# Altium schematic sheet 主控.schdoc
size 420 x 297 mm; Symbol: Drawing-Symbol_A4; Company: 嘉立创EDA; Version: V1.0; Page Size: A4; @Project Name: FOC; @Update Date: 2026-07-20; @Create Date: 2026-07-20; Device: Drawing-Symbol_A4; @Board Name: Board1; @Page Name: P1; @Create Time: 00:30:57; @Page Count: 3; @Page No: 3; @Schematic Name: Schematic1; @Update Time: 00:30:57; @Assembly Variant: Basic; Border: 1; Title Block Position: 3; Size: A4; Width: 1655; Height: 1170; Region Start: 1; X Region Count: 6; Y Region Count: 4; Blade Width: 10
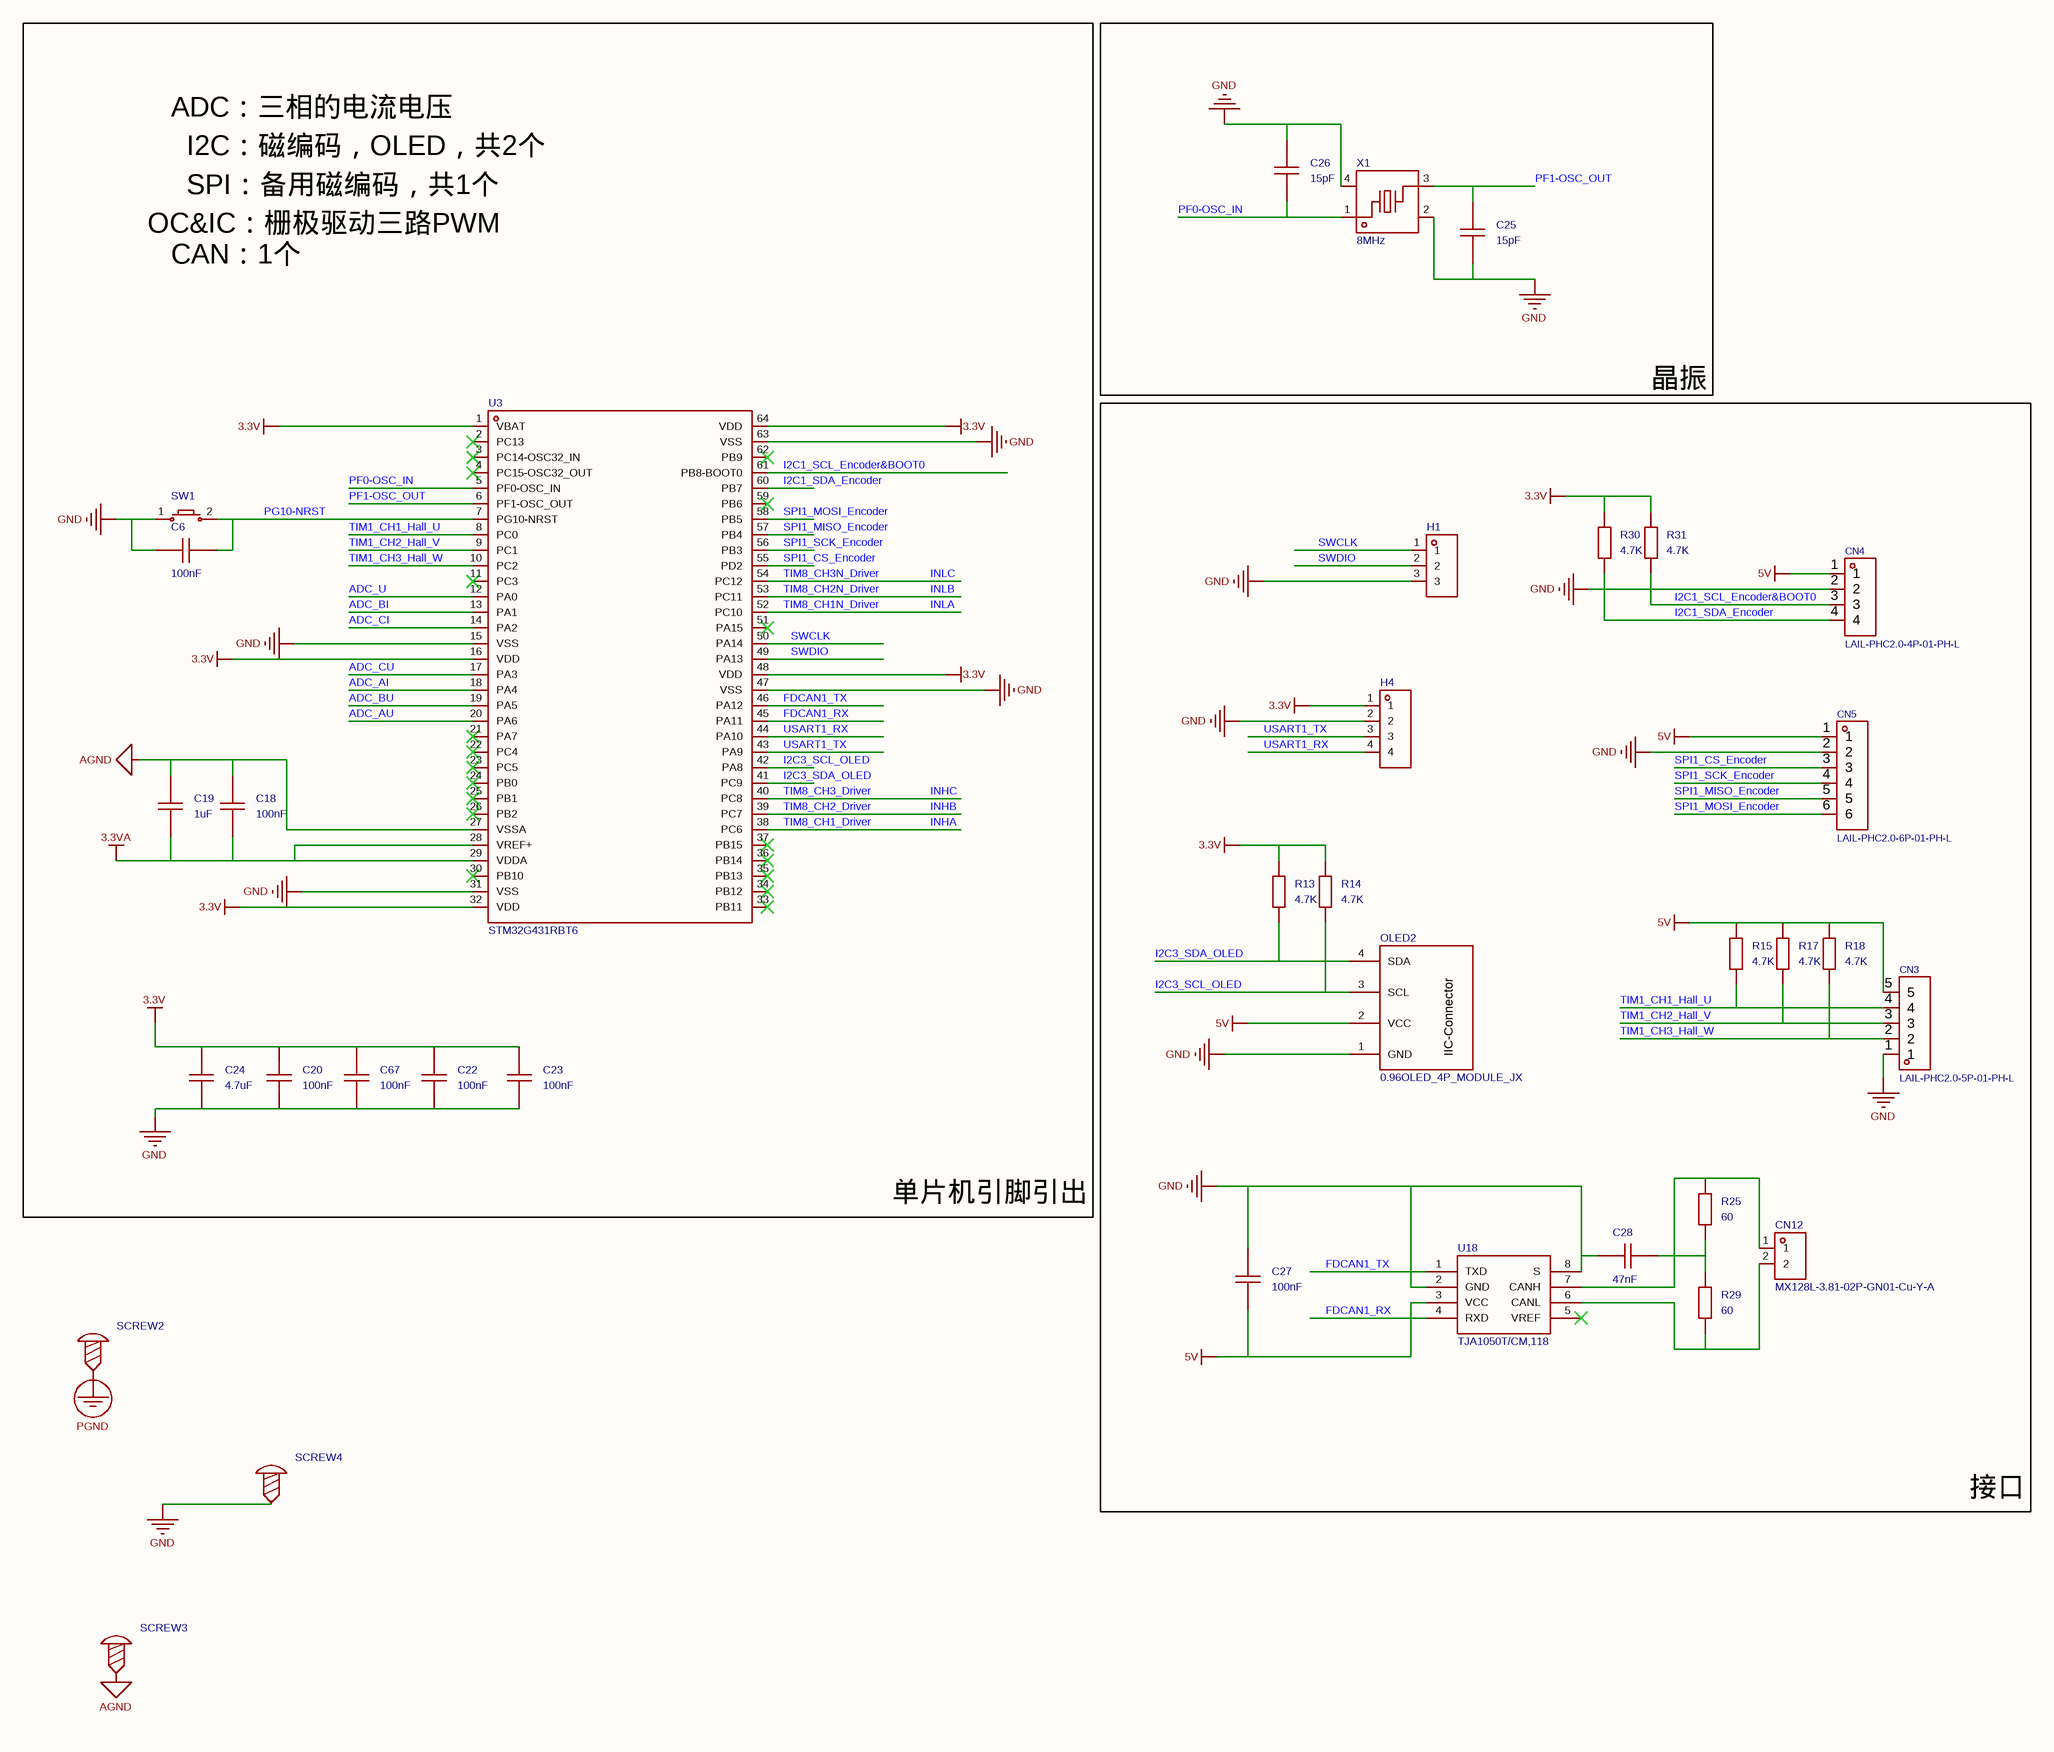
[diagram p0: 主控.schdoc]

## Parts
C6  100nF  [C0603]
C18  100nF  [C0603]
C19  1uF  [C0603]
C20  100nF  [C0603]
C22  100nF  [C0603]
C23  100nF  [C0603]
C24  4.7uF  [C0603]
C25  15pF  [C0603]
C26  15pF  [C0603]
C27  100nF  [C0603]
C28  47nF  [C0603]
C67  100nF  [C0603]
CN3  LAIL-PHC2.0-5P-01-PH-L  [CONN-TH_5P-P2.00_ZX-PH2.0-5PZZ]
CN4  LAIL-PHC2.0-4P-01-PH-L  [CONN-TH_HC-PH-4A-Y-K-10]
CN5  LAIL-PHC2.0-6P-01-PH-L  [CONN-TH_6P-P2.00_LAIL-PHC2.0-6P-01-PH-L]
CN12  MX128L-3.81-02P-GN01-Cu-Y-A  [CONN-TH_2P-P3.81_MX128L-3.81-GN01-02P-CU-Y-A]
H1  (no value)  [HDR-TH_3P-P2.54-V-M]
H4  (no value)  [HDR-TH_4P-P2.54-V-M]
OLED2  0.96OLED_4P_MODULE_JX  [0.96OLED_4P]
R13  4.7K  [R0603]
R14  4.7K  [R0603]
R15  4.7K  [R0603]
R17  4.7K  [R0603]
R18  4.7K  [R0603]
R25  60  [R0603]
R29  60  [R0603]
R30  4.7K  [R0603]
R31  4.7K  [R0603]
SCREW2  (no value)  [M3螺丝]
SCREW3  (no value)  [M3螺丝]
SCREW4  (no value)  [M3螺丝]
SW1  (no value)  [Key_SMD_3x4x2]
U3  STM32G431RBT6  [LQFP-64_L10.0-W10.0-P0.50-LS12.0-BL]
U18  TJA1050T/CM,118  [SOIC-8_L5.0-W4.0-P1.27-LS6.0-BL]
X1  8MHz  [CRYSTAL-SMD_4P-L3.2-W2.5-BL-1]

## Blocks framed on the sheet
晶振: C25 C26 X1
接口: C27 C28 CN3-CN5 CN12 H1 H4 OLED2 R13-R15 R17 R18 R25 R29-R31 U18

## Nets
3.3V: C20.2 C22.2 C23.2 C24.2 C67.2 H4.1 R13.2 R14.2 R30.2 R31.2 U3.1(VBAT) U3.16(VDD) U3.32(VDD) U3.48(VDD) U3.64(VDD)
3.3VA: C18.1 C19.1 U3.28(VREF+) U3.29(VDDA)
5V: C27.2 CN3.5 CN4.1 CN5.1 OLED2.2(VCC) R15.2 R17.2 R18.2 U18.3(VCC)
AGND: C18.2 C19.2 SCREW3.1 U3.27(VSSA)
GND: C6.1 C20.1 C22.1 C23.1 C24.1 C25.1 C26.2 C27.1 C28.1 C67.1 CN3.1 CN4.2 CN5.2 H1.3 H4.2 OLED2.1(GND) SCREW4.1 SW1.1 U3.15(VSS) U3.31(VSS) U3.47(VSS) U3.63(VSS) U18.2(GND) U18.8(S) X1.2(GND) X1.4(GND)
PGND: SCREW2.1
ADC_AI: U3.18(PA4)
ADC_AU: U3.20(PA6)
ADC_BI: U3.13(PA1)
ADC_BU: U3.19(PA5)
ADC_CI: U3.14(PA2)
ADC_CU: U3.17(PA3)
ADC_U: U3.12(PA0)
FDCAN1_RX: U3.45(PA11) U18.4(RXD)
FDCAN1_TX: U3.46(PA12) U18.1(TXD)
I2C1_SCL_Encoder&BOOT0: CN4.3 R31.1 U3.61(PB8-BOOT0)
I2C1_SDA_Encoder: CN4.4 R30.1 U3.60(PB7)
I2C3_SCL_OLED: OLED2.3(SCL) R14.1 U3.42(PA8)
I2C3_SDA_OLED: OLED2.4(SDA) R13.1 U3.41(PC9)
INHA: U3.38(PC6)  [also labelled TIM8_CH1_Driver]
INHB: U3.39(PC7)  [also labelled TIM8_CH2_Driver]
INHC: U3.40(PC8)  [also labelled TIM8_CH3_Driver]
INLA: U3.52(PC10)  [also labelled TIM8_CH1N_Driver]
INLB: U3.53(PC11)  [also labelled TIM8_CH2N_Driver]
INLC: U3.54(PC12)  [also labelled TIM8_CH3N_Driver]
PF0-OSC_IN: C26.1 U3.5(PF0-OSC_IN) X1.1
PF1-OSC_OUT: C25.2 U3.6(PF1-OSC_OUT) X1.3
PG10-NRST: C6.2 SW1.2 U3.7(PG10-NRST)
SPI1_CS_Encoder: CN5.3 U3.55(PD2)
SPI1_MISO_Encoder: CN5.5 U3.57(PB4)
SPI1_MOSI_Encoder: CN5.6 U3.58(PB5)
SPI1_SCK_Encoder: CN5.4 U3.56(PB3)
SWCLK: H1.1 U3.50(PA14)
SWDIO: H1.2 U3.49(PA13)
TIM1_CH1_Hall_U: CN3.4 R15.1 U3.8(PC0)
TIM1_CH2_Hall_V: CN3.3 R17.1 U3.9(PC1)
TIM1_CH3_Hall_W: CN3.2 R18.1 U3.10(PC2)
USART1_RX: H4.4 U3.44(PA10)
USART1_TX: H4.3 U3.43(PA9)
NetC28_2: C28.2 R25.1 R29.2
NetCN12_1: CN12.1 R25.2 U18.7(CANH)
NetCN12_2: CN12.2 R29.1 U18.6(CANL)

Not connected (* = marked no-connect by the designer): U3 2(PC13)* 3(PC14-OSC32_IN)* 4(PC15-OSC32_OUT)* 11(PC3)* 21(PA7)* 22(PC4)* 23(PC5)* 24(PB0)* 25(PB1)* 26(PB2)* 30(PB10)* 33(PB11)* 34(PB12)* 35(PB13)* 36(PB14)* 37(PB15)* 51(PA15)* 59(PB6)* 62(PB9)*; U18 5(VREF)*

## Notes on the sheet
- ADC：三相的电流电压
- I2C：磁编码，OLED，共2个
- SPI：备用磁编码，共1个
- OC&IC：栅极驱动三路PWM
- CAN：1个
- 单片机引脚引出

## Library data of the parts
C6 C18-C20 C22-C28 C67 = CAP_0603: Symbol: Capacitance; 3D Model: ac125912035d415993ca9572d50418b10819f05c4eef4c71ace90d822a990e87; 3D Model Transform: 62.992,31.496,0,0,0,0,0,0,0; ConvertToPcb: yes; ModelName: C0603_L1.6-W0.8-H0.8
CN3 = LAIL-PHC2.0-5P-01-PH-L: 插针结构:1x5P;间距:2mm;安装方式:直插;参考系列:PH;总PIN数:5P;排数:1;每排PIN数:5;额定电流:2A;触头材质:黄铜;触头镀层:锡;工作温度:-25℃~+85℃;; Manufacturer: LAILAN(莱联); AddInBom: yes; ModelId: 94ab26075ee34af38de3e49c48038e950819f05c4eef4c71ace90d822a990e87; ModelTransform: 472.8337,185.039,0,0,0,0,0,-23.622,-129.921; Pins Structure: 1x5P; Pitch: 2mm; Reference Series: PH; Number of PINs Per Row: 5; Current Rating: 2A; Voltage Rating: 250V; Plastic Material: PA66; Flame Retardant Rating: UL94V-0; Z-Height of the Board: 6mm; X-Length of Bottom Edge on Board (Spacing Line): 12mm; Y-Width of Bottom Edge on Board: 4.7mm
CN4 = LAIL-PHC2.0-4P-01-PH-L: 插针结构:1x4P;间距:2mm;安装方式:直插;参考系列:PH;总PIN数:4P;排数:1;每排PIN数:4;额定电流:2A;触头材质:黄铜;触头镀层:锡;工作温度:-25℃~+85℃;; Manufacturer: LAILAN(莱联); AddInBom: yes; ModelId: 48bf407d0722413bad2b8b1dc7f23acf0819f05c4eef4c71ace90d822a990e87; ModelTransform: 393.7,177.559,0,0,0,0,0,21.417,-122.047; Pins Structure: 1x4P; Pitch: 2mm; Reference Series: PH; Number of PINs Per Row: 4; Current Rating: 2A; Voltage Rating: 250V; Plastic Material: PA66; Flame Retardant Rating: UL94V-0; Z-Height of the Board: 6mm; X-Length of Bottom Edge on Board (Spacing Line): 10mm; Y-Width of Bottom Edge on Board: 4.7mm
CN5 = LAIL-PHC2.0-6P-01-PH-L: 插针结构:1x6P;间距:2mm;安装方式:直插;参考系列:PH;总PIN数:6P;排数:1;每排PIN数:6;额定电流:2A;触头材质:黄铜;触头镀层:锡;工作温度:-25℃~+85℃;; Manufacturer: LAILAN(莱联); AddInBom: yes; ModelId: 49b32a1e7f6d46e193f59613c5aa150c0819f05c4eef4c71ace90d822a990e87; ModelTransform: 551.18,185.078,0,0,0,0,0,25.59,-133.858; Pins Structure: 1x6P; Pitch: 2mm; Reference Series: PH; Number of PINs Per Row: 6; Current Rating: 2A; Voltage Rating: 250V; Plastic Material: PA66; Flame Retardant Rating: UL94V-0; Z-Height of the Board: 6mm; X-Length of Bottom Edge on Board (Spacing Line): 14mm; Y-Width of Bottom Edge on Board: 4.7mm
CN12 = MX128L-3.81-02P-GN01-Cu-Y-A: 结构:1x2P;间距:3.81mm;颜色:绿色;安装方式:直插;排数:1;每排PIN数:2;额定电流:10A;额定电压:150V;线规 - AWG:16~26;线规 - 平方毫米:1.5;工作温度范围:-40℃~+105℃;; Manufacturer: MAX(迈旭); Symbol: MX128L-3.81-GN01-02P-CU-Y-A; 3D Model: 3ada76795bf04056bedcd0ec9f9046df0819f05c4eef4c71ace90d822a990e87; 3D Model Transform: 300.3931,291.338,0,0,0,0,0,-11.811,-137.795; Structure: 1x2P; Pitch: 3.81mm; Number of PINs Per Row: 2; Screw Specification: M2; Current Rating (Max): 10A; Voltage Rating (Max): 150V; Wire Gauge - AWG: 16~26; Wire Gauge - mm2: 1.5; AddInBom: yes
H1 = HDR-M_2.54_1x3P: AddInBom: yes; ModelId: bb473b6d38ff42a99216a4fcdbdcc4cb0819f05c4eef4c71ace90d822a990e87; ModelName: HDR-TH_3P-P2.54-M-LI-1X3P; ModelTransform: 300.03877,100,0,0,0,0,0,0,-118.11
H4 = HDR-M_2.54_1x4P: Symbol: PZ254V-11-04P; 3D Model: 112f4d05e8d64e99ab9a333894bea4f90819f05c4eef4c71ace90d822a990e87; 3D Model Transform: 399.999,104.7242,0,0,0,0,0,0,-118.11; ConvertToPcb: yes; ModelName: HDR-TH_4P-P2.54-M-LI-1X4P
OLED2 = oled: AddInBom: yes; ModelId: 79c000fdb68d45a296c2e9bedf4f9055450f5ac3ad8e425faa0767b05d830c6d; ModelTransform: 1393.69792,1318.895,0,0,0,0,0,-560.079,-137.795
R13-R15 R17 R18 R25 R29-R31 = Res_0603: Symbol: 电阻; 3D Model: fc143cca1e79419f9cd78b61e9279f080819f05c4eef4c71ace90d822a990e87; 3D Model Transform: 31.8897,63.7794,0,90,0,0,0,0,0; ConvertToPcb: yes
SCREW2-SCREW4 = M3螺丝: Symbol: 螺丝孔; ConvertToPcb: yes
SW1 = Key_SMD_3x4x2: Symbol: 轻触按键x2; ConvertToPcb: yes; ModelId: 63599cce708d48afbce1b0db003544770819f05c4eef4c71ace90d822a990e87; ModelName: SW-SMD_L4.0-W2.9-H2-LS5.0; ModelTransform: 196.85,114.17,79.13,0,0,0,0,0,0
U3 = STM32G431RBT6: CPU内核:ARM-M系列;CPU最大主频:170MHz;应用领域:-;; Manufacturer: ST(意法半导体); AddInBom: yes; ModelId: cd9de06618c44fcf82654c43a457f83c0819f05c4eef4c71ace90d822a990e87; ModelName: LQFP-64_L10.0-W10.0-H1.4-LS12.0-P0.50; ModelTransform: 472.441,472.441,0,0,0,0,0,0.465,0; CPU Maximum Speed: 170MHz; Program Storage Size: 128KB; Number of I/O: 52; ADC (Bit): 12bit; Voltage - Supply: 1.71V~3.6V
U18 = TJA1050T/CM,118: 类型:CAN收发器;数据速率:1Mbps;; Manufacturer: NXP(恩智浦); 3D Model: 7abc64c95a1a4a04a4ef38f9097c870b0819f05c4eef4c71ace90d822a990e87; 3D Model Transform: 192.913,236.22,0,0,0,0,0,0,0; Data Rate: 1Mbps; Voltage - Supply: 4.75V~5.25V; Current - Supply: 50mA; AddInBom: yes
X1 = XL2EL89COI-111YLC-8M: 晶振类型:贴片晶振;频率:8MHz;常温频差:±10ppm;负载电容:12pF;频率稳定度:±20ppm;; Manufacturer: YXC(扬兴晶振); AddInBom: yes; ModelId: 4495b492a02c4f389e505ec8ae3aaf1b0819f05c4eef4c71ace90d822a990e87; ModelTransform: 125.984,98.425,0,0,0,0,0,0,0; Normal temperature Frequency Tolerance: ±10ppm; Load Capacitance: 12pF; Frequency Stability: ±20ppm; Equivalent Series Resistance(ESR): 150Ω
